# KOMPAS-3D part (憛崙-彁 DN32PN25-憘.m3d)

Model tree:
1. Объединить компоненты:1  (labels: СЕНС-ПР DN32PN25)
2. Эскиз:1
3. Операция выдавливания:1
     Расстояние 1 = 14; Расстояние 2 = 20.75
4. Фаска:1
     Угол = 45; Длина 1 = 2; Длина 2 = 2

Referenced files in D:\Савин\!СЕНСОР\3D для заказчика\!Новый перечень\СЕНС-ПР\1. СЕНС-ПР\DN32\: СЕНС-ПР DN32PN25.a3d
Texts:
  СЕНС-ПР DN32PN25-СВ
  ООО НПП Сенсор
  СЕНС-ПР DN32PN25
